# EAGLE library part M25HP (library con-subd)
SUB-D
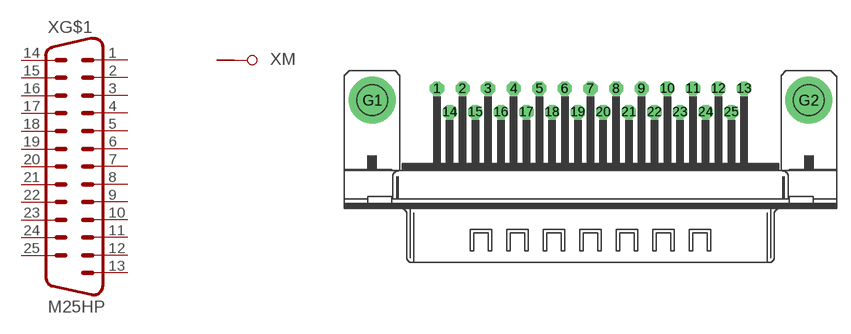
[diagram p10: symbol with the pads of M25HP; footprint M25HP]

Designator prefix X; gates G$1=M25 M=GND

## M25HP (OC_FARNELL: unknown; OC_NEWARK: unknown)  [M25HP]
1  G$1:1  pas
2  G$1:2  pas
3  G$1:3  pas
4  G$1:4  pas
5  G$1:5  pas
6  G$1:6  pas
7  G$1:7  pas
8  G$1:8  pas
9  G$1:9  pas
10  G$1:10  pas
11  G$1:11  pas
12  G$1:12  pas
13  G$1:13  pas
14  G$1:14  pas
15  G$1:15  pas
16  G$1:16  pas
17  G$1:17  pas
18  G$1:18  pas
19  G$1:19  pas
20  G$1:20  pas
21  G$1:21  pas
22  G$1:22  pas
23  G$1:23  pas
24  G$1:24  pas
25  G$1:25  pas
G1  M:G1  pas
G2  M:G2  pas

## Footprint M25HP (pad centres in mm)
SUB-D
drill 1.016 octagon: 1 -16.561,1.27; 2 -13.792,1.27; 3 -11.049,1.27; 4 -8.28,1.27; 5 -5.512,1.27; 6 -2.769,1.27; 7 0,1.27; 8 2.769,1.27; 9 5.512,1.27; 10 8.28,1.27; 11 11.049,1.27; 12 13.792,1.27; 13 16.561,1.27; 14 -15.189,-1.27; 15 -12.421,-1.27; 16 -9.652,-1.27; 17 -6.909,-1.27; 18 -4.14,-1.27; 19 -1.372,-1.27; 20 1.372,-1.27; 21 4.14,-1.27; 22 6.909,-1.27; 23 9.652,-1.27; 24 12.421,-1.27; 25 15.189,-1.27
drill 3.302 pad 5.08 round: G1 -23.52,0; G2 23.52,0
